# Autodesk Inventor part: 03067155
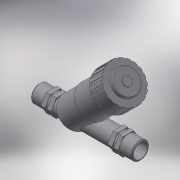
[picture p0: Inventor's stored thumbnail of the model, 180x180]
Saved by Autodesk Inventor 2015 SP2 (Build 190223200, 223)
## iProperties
Created: 2017-05
Part Number: 03067155
Material: Generic
Description: PLASSON CHECK VALVE 1.1/2"
Document SubType Name: Modeling
Designer: KIM
Mass: 228.741 g
Surface Area: 415.565 cm^2
Volume: 228.741 cm^3
Density: 1 g/cm^3
Appearance: Default
Author: KIM
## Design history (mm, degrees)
derived "03067-03068.ipt"
feature "Solid1::03067-03068.ipt"
tag "TaggingFeature1"
body "Solid1"
other parameters: "d1" = 41.91, "d2" = 46, "d3" = 33.528, "d4" = 22, "d5" = 22, "d8" = 2, "d12" = 0, "d15" = 4, "d16" = 0, "d17" = 50.652, "d18" = 7.236, "d20" = 63.315, "d21" = 135 deg, "d22" = 66.33, "d23" = 36.18, "d24" = 78.39, "d25" = 18.09, "d29" = 18.09, "d31" = 18.09, "d32" = 60.3, "d34" = 135 deg, "d35" = 2, "d36" = 120.6, "d40" = 2.68, "d80" = 76.0383, "d81" = 5.36, "d82" = 2.68, "d83" = 31.356, "d84" = 0, "d86" = 360 deg, "d88" = 1.34, "d90" = 1, "d91" = 134, "d92" = 1.809, "R_" = 41.91, "E_" = 46, "l_2" = 22, "A_" = 134, "d79" = 78.39
